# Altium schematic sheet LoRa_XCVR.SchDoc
size B
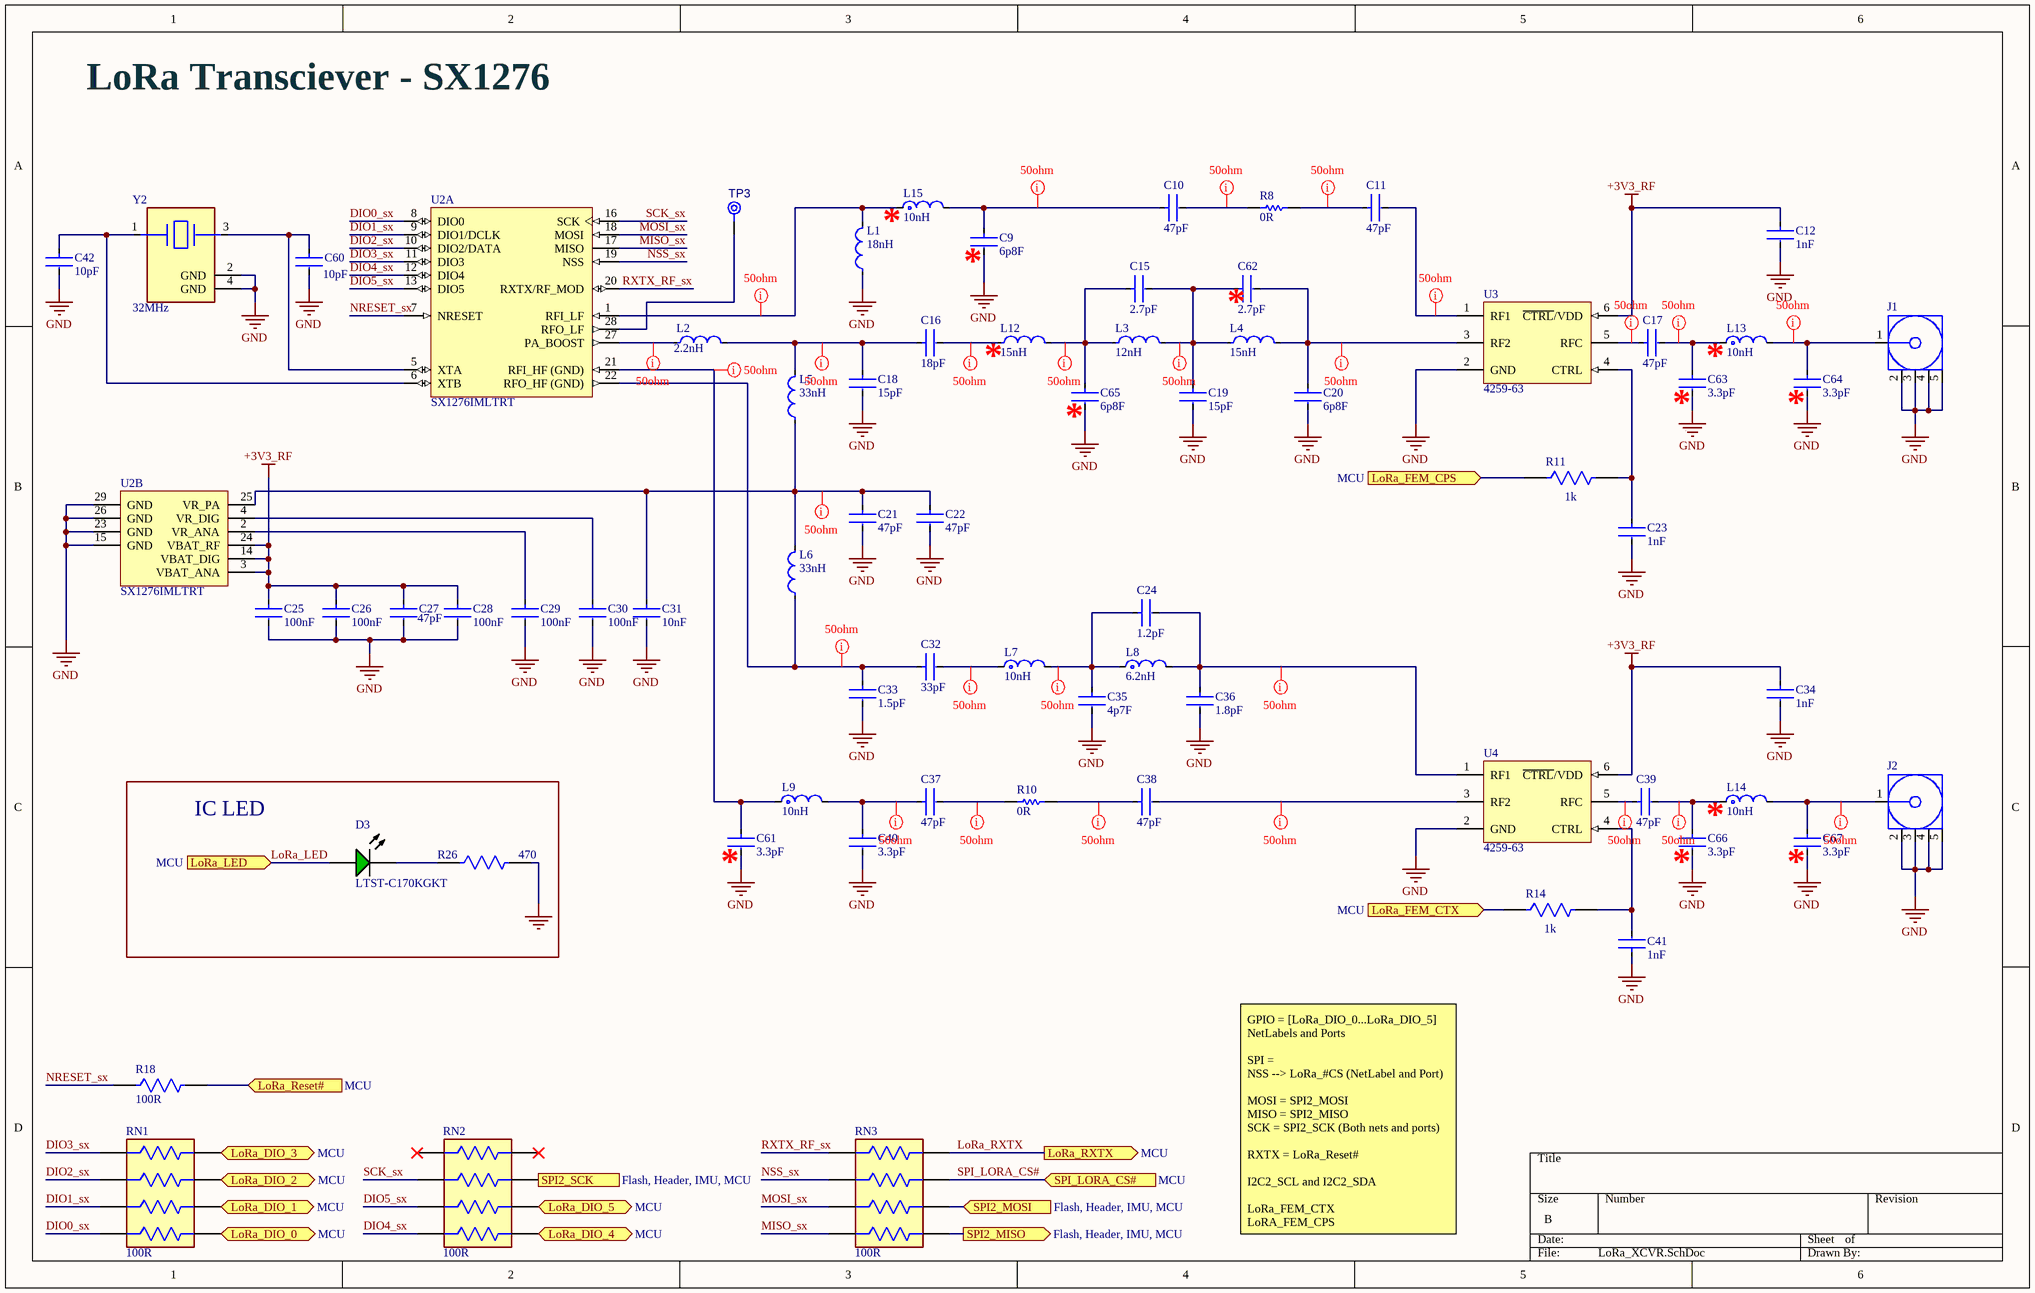
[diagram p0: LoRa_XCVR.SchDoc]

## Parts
C9  6p8F  [FP-GJM155-0_05-IPC_A]
C10  47pF  [FP-GJM155-0_05-MFG]
C11  47pF  [FP-GJM155-0_05-MFG]
C12  1nF  [FP-GRM155-0_05-IPC_C]
C15  2.7pF  [FP-GJM155-0_05-IPC_A]
C16  18pF  [FP-GJM155-0_05-IPC_B]
C17  47pF  [FP-GJM155-0_05-MFG]
C18  15pF  [FP-GJM155-0_05-IPC_A]
C19  15pF  [FP-GJM155-0_05-IPC_A]
C20  6p8F  [FP-GJM155-0_05-IPC_A]
C21  47pF  [FP-GJM155-0_05-MFG]
C22  47pF  [FP-GJM155-0_05-MFG]
C23  1nF  [FP-GRM155-0_05-IPC_C]
C24  1.2pF  [FP-GJM155-0_05-IPC_B]
C25  100nF  [FP-GRM155-0_05-IPC_B]
C26  100nF  [FP-GRM155-0_05-IPC_B]
C27  47pF  [FP-GJM155-0_05-MFG]
C28  100nF  [FP-GRM155-0_05-IPC_B]
C29  100nF  [FP-GRM155-0_05-IPC_B]
C30  100nF  [FP-GRM155-0_05-IPC_B]
C31  10nF  [FP-GRM155-0_05-IPC_C]
C32  33pF  [FP-GJM155-0_05-MFG]
C33  1.5pF  [FP-GJM155-0_05-IPC_C]
C34  1nF  [FP-GRM155-0_05-IPC_C]
C35  4p7F  [FP-GJM155-0_05-IPC_B]
C36  1.8pF  [FP-GJM155-0_05-IPC_B]
C37  47pF  [FP-GJM155-0_05-MFG]
C38  47pF  [FP-GJM155-0_05-MFG]
C39  47pF  [FP-GJM155-0_05-MFG]
C40  3.3pF  [FP-GJM155-0_05-IPC_C]
C41  1nF  [FP-GRM155-0_05-IPC_C]
C42  10pF  [FP-GRT155-0_05-MFG]
C60  10pF  [FP-GRT155-0_05-MFG]
C61  3.3pF  [FP-GJM155-0_05-IPC_C]
C62  2.7pF  [FP-GJM155-0_05-IPC_A]
C63  3.3pF  [FP-GJM155-0_05-IPC_C]
C64  3.3pF  [FP-GJM155-0_05-IPC_C]
C65  6p8F  [FP-GJM155-0_05-IPC_A]
C66  3.3pF  [FP-GJM155-0_05-IPC_C]
C67  3.3pF  [FP-GJM155-0_05-IPC_C]
D3  LTST-C170KGKT  [LTST-LTST-C170KGKT-2_V]
J1  142-0701-801  [CINC-142-0701-801_V]  (value not drawn)
J2  142-0701-801  [CINC-142-0701-801_V]  (value not drawn)
L1  18nH  [FP-LQW15AN_00-W0_6-0_1-MFG]
L2  2.2nH  [FP-LQW15AN_00-W0_6-0_1-MFG]
L3  12nH  [FP-LQW15AN_00-W0_6-0_1-MFG]
L4  15nH  [FP-LQW15AN_00-W0_6-0_1-MFG]
L5  33nH  [FP-LQW15AN_00-W0_5-0_1-MFG]
L6  33nH  [FP-LQW15AN_00-W0_5-0_1-MFG]
L7  10nH  [FP-LQG15HH_02-IPC_A]
L8  6.2nH  [FP-LQG15HH_02-IPC_C]
L9  10nH  [FP-LQG15HH_02-IPC_A]
L12  15nH  [FP-LQW15AN_00-W0_6-0_1-MFG]
L13  10nH  [FP-LQG15HH_02-IPC_A]
L14  10nH  [FP-LQG15HH_02-IPC_A]
L15  10nH  [FP-LQG15HH_02-IPC_A]
R8  0R  [RESC1005X40X25LL05T05]
R10  0R  [RESC1005X40X25LL05T05]
R11  1k  [FP-CRCW0402-e3-MFG]
R14  1k  [FP-CRCW0402-e3-MFG]
R18  100R  [FP-CRCW0402-e3-IPC_A]
R26  470  [FP-CPF0603-MFG]
RN1  100R  [FP-EXB38V-MFG]
RN2  100R  [FP-EXB38V-MFG]
RN3  100R  [FP-EXB38V-MFG]
TP3  TPAD6R  [TP06R]  (value not drawn)  (no BOM)
U2  SX1276IMLTRT  [SMTC-QFN-28_V]  (parts A,B of 2)
U3  4259-63  [PERE-SC-70-6_M]
U4  4259-63  [PERE-SC-70-6_M]
Y2  32MHz  [FP-ABM11-MFG]

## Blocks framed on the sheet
IC LED: D3 R26

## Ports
LoRa_DIO_0 (bidir, see MCU), LoRa_DIO_1 (bidir, see MCU), LoRa_DIO_2 (bidir, see MCU), LoRa_DIO_3 (bidir, see MCU), LoRa_DIO_4 (bidir, see MCU), LoRa_DIO_5 (bidir, see MCU), LoRa_FEM_CPS (in, see MCU), LoRa_FEM_CTX (in, see MCU), LoRa_LED (in, see MCU), LoRa_Reset# (in, see MCU), LoRa_RXTX (out, see MCU), SPI2_MISO (out, see Flash, Header, IMU, MCU), SPI2_MOSI (in, see Flash, Header, IMU, MCU), SPI2_SCK (in, see Flash, Header, IMU, MCU), SPI_LORA_CS# (in, see MCU)

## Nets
+3V3_RF: C12.1 C25.1 C26.1 C27.1 C28.1 C34.1 U2.3(VBAT_ANA) U2.14(VBAT_DIG) U2.24(VBAT_RF) U3.6(~{CTRL}/VDD) U4.6(~{CTRL}/VDD)
GND: C9.2 C12.2 C18.2 C19.2 C20.2 C21.2 C22.2 C23.2 C25.2 C26.2 C27.2 C28.2 C29.2 C30.2 C31.2 C33.2 C34.2 C35.2 C36.2 C40.2 C41.1 C42.2 C60.2 C61.2 C63.2 C64.2 C65.2 C66.2 C67.2 J1.2 J1.3 J1.4 J1.5 J2.2 J2.3 J2.4 J2.5 L1.1 R26.2 U2.15(GND) U2.23(GND) U2.26(GND) U2.29(GND) U3.2(GND) U4.2(GND) Y2.2(GND) Y2.4(GND)
DIO0_sx: RN1.4 U2.8(DIO0)
DIO1_sx: RN1.3 U2.9(DIO1/DCLK)
DIO2_sx: RN1.2 U2.10(DIO2/DATA)
DIO3_sx: RN1.1 U2.11(DIO3)
DIO4_sx: RN2.4 U2.12(DIO4)
DIO5_sx: RN2.3 U2.13(DIO5)
LoRa_DIO_0: RN1.5 ; port LoRa_DIO_0
LoRa_DIO_1: RN1.6 ; port LoRa_DIO_1
LoRa_DIO_2: RN1.7 ; port LoRa_DIO_2
LoRa_DIO_3: RN1.8 ; port LoRa_DIO_3
LoRa_DIO_4: RN2.5 ; port LoRa_DIO_4
LoRa_DIO_5: RN2.6 ; port LoRa_DIO_5
LoRa_FEM_CPS: R11.1 ; port LoRa_FEM_CPS
LoRa_FEM_CTX: R14.1 ; port LoRa_FEM_CTX
LoRa_LED: D3.2(A) ; port LoRa_LED
LoRa_Reset#: R18.2 ; port LoRa_Reset#
LoRa_RXTX: RN3.8 ; port LoRa_RXTX
MISO_sx: RN3.4 U2.17(MISO)
MOSI_sx: RN3.3 U2.18(MOSI)
NRESET_sx: R18.1 U2.7(NRESET)
NSS_sx: RN3.2 U2.19(NSS)
RXTX_RF_sx: RN3.1 U2.20(RXTX/RF_MOD)
SCK_sx: RN2.2 U2.16(SCK)
SPI2_MISO: RN3.5 ; port SPI2_MISO
SPI2_MOSI: RN3.6 ; port SPI2_MOSI
SPI2_SCK: RN2.7 ; port SPI2_SCK
SPI_LORA_CS#: RN3.7 ; port SPI_LORA_CS#
NetC9_1: C9.1 C10.1 L15.2
NetC10_2: C10.2 R8.1
NetC11_1: C11.1 R8.2
NetC11_2: C11.2 U3.1(RF1)
NetC15_1: C15.1 C65.1 L3.1 L12.2
NetC15_2: C15.2 C19.1 C62.1 L3.2 L4.1
NetC16_1: C16.1 C18.1 L2.2 L5.2
NetC16_2: C16.2 L12.1
NetC17_1: C17.1 U3.5(RFC)
NetC17_2: C17.2 C63.1 L13.1
NetC20_1: C20.1 C62.2 L4.2 U3.3(RF2)
NetC21_1: C21.1 C22.1 C31.1 L5.1 L6.2 U2.25(VR_PA)
NetC23_1: C23.1 R11.2 U3.4(CTRL)
NetC24_1: C24.1 C35.1 L7.2 L8.1
NetC24_2: C24.2 C36.1 L8.2 U4.1(RF1)
NetC29_1: C29.1 U2.2(VR_ANA)
NetC30_1: C30.1 U2.4(VR_DIG)
NetC32_1: C32.1 C33.1 L6.1 U2.22(RFO_HF_(GND))
NetC32_2: C32.2 L7.1
NetC37_1: C37.1 C40.1 L9.2
NetC37_2: C37.2 R10.1
NetC38_1: C38.1 R10.2
NetC38_2: C38.2 U4.3(RF2)
NetC39_1: C39.1 U4.5(RFC)
NetC39_2: C39.2 C66.1 L14.1
NetC41_2: C41.2 R14.2 U4.4(CTRL)
NetC42_1: C42.1 U2.6(XTB) Y2.1
NetC60_1: C60.1 U2.5(XTA) Y2.3
NetC61_1: C61.1 L9.1 U2.21(RFI_HF_(GND))
NetC64_1: C64.1 J1.1 L13.2
NetC67_1: C67.1 J2.1 L14.2
NetD3_1: D3.1(K) R26.1
NetL1_2: L1.2 L15.1 U2.1(RFI_LF)
NetL2_1: L2.1 U2.27(PA_BOOST)
NetTP3_1: TP3.1(TP) U2.28(RFO_LF)

Not connected (* = marked no-connect by the designer): RN2 1* 8*

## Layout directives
net class 50ohm: NetC9_1, NetC10_2, NetC11_1, NetC11_2, NetC15_1, NetC15_2, NetC16_1, NetC16_2, NetC17_1, NetC17_2, NetC20_1, NetC21_1, NetC24_1, NetC24_2, NetC32_1, NetC32_2, NetC37_1, NetC37_2, NetC38_1, NetC38_2, NetC39_1, NetC39_2, NetC61_1, NetC64_1, NetC67_1, NetL1_2, NetL2_1

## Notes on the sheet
- LoRa Transciever - SX1276
- (near L15) *
- (near C9) *
- (near L12) *
- (near C62) *
- (near L13) *
- (near C65) *
- (near C63) *
- (near C64) *
- (near L14) *
- (near C61) *
- (near C66) *
- (near C67) *
- GPIO = [LoRa_DIO_0...LoRa_DIO_5] NetLabels and Ports
  SPI =
  NSS --> LoRa_#CS (NetLabel and Port)
  MOSI = SPI2_MOSI
  MISO = SPI2_MISO
  SCK = SPI2_SCK (Both nets and ports)
  RXTX = LoRa_Reset#
  I2C2_SCL and I2C2_SDA
  LoRa_FEM_CTX
  LoRA_FEM_CPS

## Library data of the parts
C9 C20 C65 = CMP-2008-03772-2: Multi-Layer Ceramic Capacitor 6.8pF C0G  ±0.1pF 0402 Paper T/R; Voltage Rating (DC): 50V
C10 C11 C17 C21 C22 C27 C37-C39 = CMP-06035-013708-1: Multi-Layer Ceramic Capacitor 47pF C0G  ±5% 0402 Paper T/R; Voltage Rating (DC): 50V
C12 C23 C34 C41 = CMP-1034-01633-3: Chip Multilayer Ceramic Capacitors for General Purpose, 0402, 1000pF, X7R, 15%, 10%, 100V
C15 C62 = CMP-2008-03840-2: Multi-Layer Ceramic Capacitor 2.7pF C0G  ±0.1pF 0402 Paper T/R; Voltage Rating (DC): 50V; Temperature Coefficient: 30ppm/°C
C16 = CMP-2008-03807-2: Multi-Layer Ceramic Capacitor 18pF C0G  ±5% 0402 Paper T/R; Voltage: 50V
C18 C19 = CMP-2008-03804-2: Multi-Layer Ceramic Capacitor 15pF C0G  ±5% 0402 Paper T/R; Voltage Rating (DC): 50V; Temperature Coefficient: 30ppm/°C
C24 = CMP-2008-03813-2: Multi-Layer Ceramic Capacitor 1.2pF C0G  ±0.1pF 0402 Paper T/R; Voltage Rating (DC): 50V; Temperature Coefficient: 30ppm/°C
C25 C26 C28-C30 = CMP-2008-04639-2: Chip Multilayer Ceramic Capacitors for General Purpose, 0402, 0.10uF, X7R, 15%, 10%, 50V; Dissipation Factor: 0.025%
C31 = CMP-2008-04637-5: Chip Multilayer Ceramic Capacitors for General Purpose, 0402, 10000pF, X7R, 15%, 10%, 50V; Voltage: 25V
C32 = CMP-06035-057988-1: Multi-Layer Ceramic Capacitor 33pF C0G  ±5% 0402 Paper T/R; Voltage Rating (DC): 50V
C33 = CMP-2008-03820-2: Multi-Layer Ceramic Capacitor 1.5pF C0G  ±0.1pF 0402 Paper T/R; Temperature Coefficient: 30ppm/°C; Voltage Rating: 50V
C35 = CMP-2008-03859-2: Multi-Layer Ceramic Capacitor 4.7pF C0G  ±0.25pF 0402 Paper T/R; Voltage Rating (DC): 50V; Temperature Coefficient: 30ppm/°C
C36 = CMP-2008-03825-2: Multi-Layer Ceramic Capacitor 1.8pF C0G  ±0.1pF 0402 Paper T/R; Voltage: 50V
C40 C61 C63 C64 C66 C67 = CMP-2008-03846-2: Multi-Layer Ceramic Capacitor 3.3pF C0G  ±0.1pF 0402 Paper T/R; Voltage: 50V
C42 C60 = CMP-06035-051459-1: Multi-Layer Ceramic Capacitor 10pF 50V C0G ±5% 0402 Paper T/R
D3 = CMP-2000-06620-1: Ultra Bright AlInGaP Chip LED, 75 mW, -55 to 85 degC, 2-Pin SMD (0805), RoHS, Tape and Reel; Manufacturer: Lite-On; Forward Current: 30mA; Power Dissipation Max: 75mW; Emitting Color: YellowGreen; Type: Uni-Color; Forward Voltage: 2.4V; Dominant Wave Length: 571nm; Test Current (It): 20mA; Product Length (mm): 2mm; Peak Wavelength: 574nm; Power Dissipation: 75W; Product Depth (mm): 1.25mm; DELETED: Compliant; High Brightness: Yes; Product Height (mm): 1.1mm; Luminous Intensity: 35mcd; Shape Type: Rectangular; Chip Material: AlGaInP; Viewing Angle: 130deg; Number of  Elements: 1; Reverse Voltage: 5V; Rad Hardened: No
J1 J2 = CMP-2000-05490-1: SMA End Launch Jack Receptacle, 50 Ohm, 0 to 18 GHz, -65 to 165 degC, 5-Pin SMD, RoHS, Bulk; Manufacturer: EmersonConnectivitySolutions; Connector Type: JackPCB; Gender: Jack(Female); Impedance: 50Ohms; Brand: Johnson/EmersonConnectivitySolutions; Body Material: Brass; Body Style: Straight; Maximum Frequency: 18GHz
L1 = CMP-06042-006916-1: Wire Wound RF Inductor 18nH ±5% 370mA 0.27Ω 0402 (1005); Q Factor: 25; DC Resistance (DCR): 270mR; Test Frequency: 100MHz; Self Resonant Frequency: 4.5GHz; Core Material: Air; Shielding: Unshielded
L2 = CMP-06042-008786-1: Wire Wound RF Inductor 2.2nH ±0.2nH 1000mA 0.027Ω 0402 (1005); Q Factor: 25; Current Rating: 1A; Core Material: Air; Test Frequency: 100MHz; Shielding: Unshielded; DC Resistance (DCR): 27mR; Self Resonant Frequency: 14GHz
L3 = CMP-06042-005424-1: Wire Wound RF Inductor 12nH ±5% 500mA 0.14Ω 0402 (1005); Shielding: Unshielded; Self Resonant Frequency: 5.5GHz; Core Material: Air; Test Frequency: 100MHz; Q Factor: 30; DC Resistance (DCR): 140mR
L4 L12 = CMP-2000-06595-2: Wire Wound RF Inductor 15nH ±5% 460mA 0.16Ω 0402 (1005); Test Frequency: 100MHz; DC Resistance (DCR): 160mR; Shielding: Unshielded; Q Factor: 30; Core Material: Air; Self Resonant Frequency: 5GHz
L5 L6 = CMP-06042-007456-1: Wire Wound RF Inductor 33nH ±5% 260mA 0.63Ω 0402 (1005); Test Frequency: 100MHz; Core Material: Air; Shielding: Unshielded; Q Factor: 25; Self Resonant Frequency: 3.2GHz; DC Resistance (DCR): 630mR
L7 L9 L13-L15 = CMP-06042-014117-1: Multilayer type RF Inductor 10nH ±5% 0.26Ω 500mA 0402; DC Resistance (DCR): 260mR; DC Current: 300mA; Shielding: Unshielded; Q Factor: 8; Test Frequency: 100MHz; Self Resonant Frequency: 3.4GHz; Core Material: Air
L8 = CMP-06042-008294-1: Multilayer type RF Inductor 6.2nH ±0.3nH 0.2Ω 600mA 0402; Current Rating: 300mA; DC Resistance (DCR): 220mR; Shielding: Unshielded; Q Factor: 8; Test Frequency: 100MHz; Core Material: Air; Self Resonant Frequency: 4.5GHz
R8 R10 = CMP-2000-07451-1: Chip Resistor, 0 Ohm, 0.1 W, -55 to 155 degC, 0402 (1005 Metric), RoHS, Tape and Reel; Manufacturer: Panasonic; Voltage Rating (DC): 50V; Temperature Coefficient: 600ppm/��C; Max Power Dissipation: 100mW; Resistance: 0mOhm; Tolerance: 5%
R11 R14 = CMP-1011-00074-3: RES Thick Film, 1kΩ, 5%, 0.063W, 200ppm/°C, 0402; Voltage Rating: 50V; Max Power Dissipation: 63mW; Resistance: 1kR
R18 = CMP-2002-08129-2: RES Thick Film, 100Ω, 5%, 0.063W, 200ppm/°C, 0402; Working Voltage: 50V; Max Power Dissipation: 63mW
R26 = CMP-03211-004765-1: RES SMD 470Ω 0.1% 1/16W 0603 / CPF0603B470RE; Manufacturer: TE Connectivity; Temperature Coefficient: 25ppm/°C; Voltage Rating: 50V; Power Rating: 0.063W
RN1-RN3 = CMP-05421-000004-1: RES ARRAY 4 RES 100 OHM 1206; Number of Resistors: 4; Number of Terminals/Pins: 8; Voltage Rating: 50V; Resistance Tolerance: 5%; Voltage Rating (DC): 100V; Power Per Element: 62.5mW; Temperature Coefficient: 200ppm/°C; Circuit Type: Isolated
TP3 = CMP-00028-00002-2: 0.6mm round
U2 = CMP-2000-05356-1: Low Power Long Range Transceiver, 137 to 1020 MHz, -40 to 85 degC, 28-Pin QFN, RoHS, Tape and Reel; Manufacturer: Semtech; Power - Output: 20dBm; Data Rate (Max): 300kbps; Sensitivity: -148dBm; Featured Product: SX1276LongRangeTransceiver; PCN Design/Specification: CopperWire25/Mar/2014; GPIO: 6; Frequency: 137MHz~1.02GHz; Voltage - Supply: 1.8V~3.7V; Protocol: LoRa™; Current - Transmitting: 20mA~120mA; Current - Receiving: 10.8mA~12mA; Online Catalog: SX1276,SX1277andSX1278; Design Resources: SX127xReferenceDesignOverviewDevelopmentToolSelector; Serial Interfaces: SPI; Mfg Application Notes: LoRaModulation:CrystalOscillatorGuidanceSX12xxSoftwareImplementationofDataWhiteningandCRCSX127xLoRaLowEnergyDesignGuideSX127xLoRaModemDesignersGuide; Modulation: FSK,GFSK,GMSK,MSK,OOK; Other Names: SX1276IMLTRTTR
U3 U4 = CMP-2000-05298-1: IC RF Switch SPDT, 50 Ohm, 6-Pin SC70, RoHS, Tape and Reel; Manufacturer: Peregrine Semiconductor; P1dB: 29dBm(typ)IP1dB; Topology: Reflective; Frequency - Upper: 3GHz; Insertion Loss @ Frequency: 0.5dB@2GHz; IIP3: 55dBm(typ); Voltage - Supply: 1.8V~3.3V; Other Names: 1046-1011-24259-63-ND425963PE4259PE4259SCBC-ZPE4259SCBC-Z-ND; Isolation @ Frequency: 20dB@2GHz(typ); Frequency - Lower: 10MHz; Online Catalog: PE4259; Impedance: 50Ohm; RF Type: GeneralPurpose
Y2 = CMP-27762-009665-1: Crystal 32MHz ±10ppm 10pF SMD-4 2mm x 1.6mm; ESR (Equivalent Series Resistance): 80R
